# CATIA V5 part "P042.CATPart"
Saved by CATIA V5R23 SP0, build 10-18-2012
Part number: P042
Definition: Goupille élastique
Description: Goupille élastique fendu (d8-50)
Bounding box of the stored display mesh (mm): x -50 to 0, y -4 to 3.985, z -3.996 to 3.996
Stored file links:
  C:\wamp\www\COURS\CONCEPTION GMP1\TITRE 02-SEMESTRE 2\03-TP7-PRESSE MECANIQUE\eleve\P042.CATPart
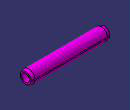
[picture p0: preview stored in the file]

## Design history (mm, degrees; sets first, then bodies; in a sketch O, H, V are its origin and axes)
Parameters
  Material = "St"
  d1_pin_nom_dia = 8 mm
  l_pin_length_nom = 50 mm
  d2_pin_id = 5.5 mm
  a_cham_max = 2 mm
  s_wall_th = 1.5 mm
  PartNumber = "Goupille elastique ISO 8752 8x50"
Set1
  Point1: (-25, 0, 0)
Body1 "PartBody" (main body)
  Sketch1 on zx-plane, origin (0, 0, 0), H (-1, 0, 0), V (0, 0, 1)
    point P1 (0, 3.4641)
    line L1 (0, 3.4641) -> (2, 4)
    point P2 (2, 4)
    point P3 (2, 4)
    line L2 (2, 4) -> (48, 4)
    point P4 (48, 4)
    line L3 (48, 4) -> (50, 3.4641)
    point P5 (50, 3.4641)
    point P6 (50, 3.4641)
    line L4 (50, 3.4641) -> (50, 2.5)
    line L5 (50, 2.5) -> (0, 2.5)
    line L6 (0, 2.5) -> (0, 3.4641)
    axis line L7 (-9.3888, 0) -> (37.524, 0)
    distance P1 L4 = 50 {= l_pin_length_nom}
    distance L5 L2 = 1.5 {= s_wall_th}
    angle L3 L2 = 15
    angle L1 L2 = 15
    distance L2 L7 = 4 {= d1_pin_nom_dia /2}
    distance V P2 = 2 {= a_cham_max}
    distance P4 P5 H = 2 {= a_cham_max}
    coincidence: P3 L1, P6 L3, P2 P3, P5 P6, P1 V
    horizontal: L2 H, L5 H, L7 H
    vertical: L4 V, L6 V
    fix: L7
  Shaft1: profile Sketch1, axis Sketch1.L7, angle 445, second angle -95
